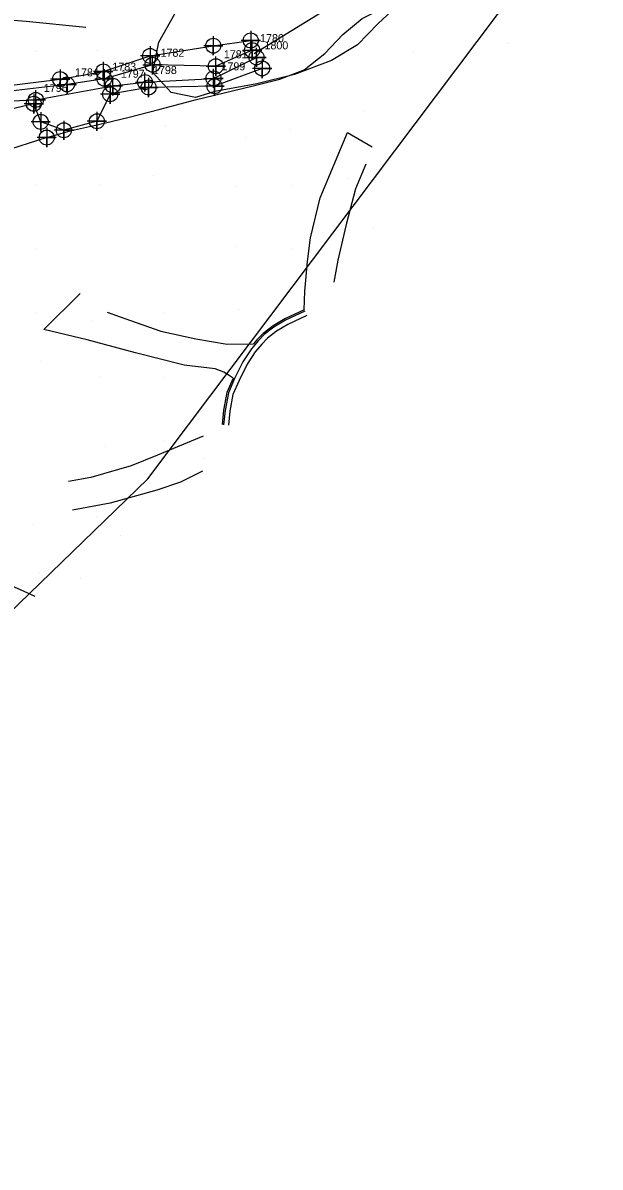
# Model space of a CAD drawing. Extents: x 1497074 to 1501343, y 481943 to 486114.
# Drawn here: x 1498743.8 to 1498924.2, y 484438.2 to 484795.7 of the extents above; entities that cross this region are included whole.
import ezdxf

# ---------------------------------------------------------------- set-up
doc = ezdxf.new("R2010")
doc.units = 0
for name, color, linetype in [('Exist DTM Breakline', 7, 'Continuous'), ('Exist DTM Breakline Cogo Point CELL', 7, 'Continuous'), ('Exist Hydro Stream or Body of Water', 7, 'Continuous'), ('Exist Hydro Stream or Body of Water Cogo Number', 7, 'Continuous'), ('Exist Hydro Stream or Body of Water Cogo Point CELL', 7, 'Continuous'), ('PH Exist DTM Boundary', 7, 'Continuous'), ('PH Exist DTM Breakline', 7, 'Continuous'), ('PH Exist DTM Obscure Area', 7, 'Continuous'), ('PH Exist DTM Point', 7, 'Continuous')]:
    doc.layers.add(name, color=color, linetype=linetype)

msp = doc.modelspace()

# ---------------------------------------------------------------- linework, layer by layer
at = {"layer": 'Exist DTM Breakline'}
for points in [[(1498642.2, 484728.41), (1498666.42, 484741.46), (1498690.37, 484749.54), (1498707.14, 484761.75), (1498724.39, 484768.67), (1498731.03, 484775.11), (1498755.48, 484778.15), (1498768.96, 484780.57), (1498783.61, 484785.4), (1498803.34, 484788.6), (1498815.05, 484790.23)], [(1498818.6, 484781.5), (1498803.72, 484775.91), (1498783.12, 484775.55), (1498771.11, 484773.41), (1498766.97, 484764.97), (1498756.64, 484762.17), (1498749.4, 484764.8), (1498747.24, 484770.45), (1498734.31, 484767.43), (1498718.71, 484759.53), (1498707.65, 484753), (1498690.86, 484741.59), (1498675.18, 484734.94)], [(1498751.28, 484759.9), (1498722.71, 484750.7), (1498697.19, 484737.24), (1498663.06, 484720.07)]]:
    msp.add_lwpolyline(points, dxfattribs=at)
at = {"layer": 'Exist DTM Breakline Cogo Point CELL'}
for points in [[(1498803.34, 484791.6), (1498803.34, 484785.6), (1498803.34, 484788.6), (1498806.34, 484788.6), (1498800.34, 484788.6)], [(1498815.05, 484793.23), (1498815.05, 484787.23), (1498815.05, 484790.23), (1498818.05, 484790.23), (1498812.05, 484790.23)], [(1498783.61, 484788.4), (1498783.61, 484782.4), (1498783.61, 484785.4), (1498786.61, 484785.4), (1498780.61, 484785.4)], [(1498818.6, 484784.5), (1498818.6, 484778.5), (1498818.6, 484781.5), (1498821.6, 484781.5), (1498815.6, 484781.5)], [(1498755.48, 484781.15), (1498755.48, 484775.15), (1498755.48, 484778.15), (1498758.48, 484778.15), (1498752.48, 484778.15)], [(1498768.96, 484783.57), (1498768.96, 484777.57), (1498768.96, 484780.57), (1498771.96, 484780.57), (1498765.96, 484780.57)], [(1498783.12, 484778.55), (1498783.12, 484772.55), (1498783.12, 484775.55), (1498786.12, 484775.55), (1498780.12, 484775.55)], [(1498803.72, 484778.91), (1498803.72, 484772.91), (1498803.72, 484775.91), (1498806.72, 484775.91), (1498800.72, 484775.91)], [(1498747.24, 484773.45), (1498747.24, 484767.45), (1498747.24, 484770.45), (1498750.24, 484770.45), (1498744.24, 484770.45)], [(1498771.11, 484776.41), (1498771.11, 484770.41), (1498771.11, 484773.41), (1498774.11, 484773.41), (1498768.11, 484773.41)], [(1498749.4, 484767.8), (1498749.4, 484761.8), (1498749.4, 484764.8), (1498752.4, 484764.8), (1498746.4, 484764.8)], [(1498766.97, 484767.97), (1498766.97, 484761.97), (1498766.97, 484764.97), (1498769.97, 484764.97), (1498763.97, 484764.97)], [(1498751.28, 484762.9), (1498751.28, 484756.9), (1498751.28, 484759.9), (1498754.28, 484759.9), (1498748.28, 484759.9)], [(1498756.64, 484765.17), (1498756.64, 484759.17), (1498756.64, 484762.17), (1498759.64, 484762.17), (1498753.64, 484762.17)]]:
    msp.add_lwpolyline(points, dxfattribs=at)
for centre in [(1498803.34, 484788.6), (1498815.05, 484790.23), (1498783.61, 484785.4), (1498818.6, 484781.5), (1498755.48, 484778.15), (1498768.96, 484780.57), (1498783.12, 484775.55), (1498803.72, 484775.91), (1498771.11, 484773.41), (1498747.24, 484770.45), (1498749.4, 484764.8), (1498766.97, 484764.97), (1498756.64, 484762.17), (1498751.28, 484759.9)]:
    msp.add_circle(centre, 2.34, dxfattribs=at)
at = {"layer": 'Exist Hydro Stream or Body of Water'}
for points in [[(1498815.48, 484787.21), (1498804.14, 484782.17), (1498784.36, 484782.64), (1498769.3, 484778.28), (1498757.64, 484776.52), (1498731.04, 484773.39), (1498724.7, 484767.33), (1498709.42, 484760.65), (1498690.59, 484748.07), (1498666.52, 484739.44), (1498641.87, 484726.36)], [(1498672.43, 484739.05), (1498689.81, 484742.76), (1498705.79, 484752.75), (1498717.83, 484761.59), (1498732.54, 484771.06), (1498747.88, 484771.66), (1498771.96, 484776.08), (1498782, 484777.24), (1498803.41, 484778.39), (1498816.84, 484784.96)]]:
    msp.add_lwpolyline(points, dxfattribs=at)
at = {"layer": 'Exist Hydro Stream or Body of Water Cogo Point CELL'}
for points in [[(1498812.48, 484787.21), (1498818.48, 484787.21), (1498815.48, 484787.21), (1498815.48, 484784.21), (1498815.48, 484790.21)], [(1498813.84, 484784.96), (1498819.84, 484784.96), (1498816.84, 484784.96), (1498816.84, 484781.96), (1498816.84, 484787.96)], [(1498781.36, 484782.64), (1498787.36, 484782.64), (1498784.36, 484782.64), (1498784.36, 484779.64), (1498784.36, 484785.64)], [(1498801.14, 484782.17), (1498807.14, 484782.17), (1498804.14, 484782.17), (1498804.14, 484779.17), (1498804.14, 484785.17)], [(1498766.3, 484778.28), (1498772.3, 484778.28), (1498769.3, 484778.28), (1498769.3, 484775.28), (1498769.3, 484781.28)], [(1498779, 484777.24), (1498785, 484777.24), (1498782, 484777.24), (1498782, 484774.24), (1498782, 484780.24)], [(1498800.41, 484778.39), (1498806.41, 484778.39), (1498803.41, 484778.39), (1498803.41, 484775.39), (1498803.41, 484781.39)], [(1498754.64, 484776.52), (1498760.64, 484776.52), (1498757.64, 484776.52), (1498757.64, 484773.52), (1498757.64, 484779.52)], [(1498768.96, 484776.08), (1498774.96, 484776.08), (1498771.96, 484776.08), (1498771.96, 484773.08), (1498771.96, 484779.08)], [(1498744.88, 484771.66), (1498750.88, 484771.66), (1498747.88, 484771.66), (1498747.88, 484768.66), (1498747.88, 484774.66)]]:
    msp.add_lwpolyline(points, dxfattribs=at)
for centre in [(1498815.48, 484787.21), (1498784.36, 484782.64), (1498804.14, 484782.17), (1498816.84, 484784.96), (1498769.3, 484778.28), (1498803.41, 484778.39), (1498757.64, 484776.52), (1498771.96, 484776.08), (1498782, 484777.24), (1498747.88, 484771.66)]:
    msp.add_circle(centre, 2.34, dxfattribs=at)
at = {"layer": 'PH Exist DTM Boundary'}
msp.add_lwpolyline([(1498186.43, 484771.69), (1498560.82, 484438.23), (1498782.89, 484653.31), (1498924.23, 484841.06), (1498545.19, 485168.9), (1498406.94, 484985.26)], close=True, dxfattribs=at)
at = {"layer": 'PH Exist DTM Breakline'}
for points in [[(1498871.75, 484817.91), (1498862.06, 484812.48), (1498844.48, 484803.59), (1498816.16, 484786.08)], [(1498751.28, 484759.9), (1498758.99, 484762.13), (1498767.46, 484763.96), (1498776.63, 484766.15), (1498786.71, 484768.77), (1498797.68, 484771.65), (1498806.73, 484773.91), (1498815.79, 484776.07), (1498824.19, 484778.19), (1498831.77, 484781.06), (1498838.18, 484786.15), (1498843.82, 484792.08), (1498849.87, 484797.11), (1498857.7, 484800.99), (1498865.48, 484804.27), (1498872, 484807.32), (1498879.68, 484809.61), (1498887.65, 484811.86), (1498895.42, 484813.08), (1498901.06, 484810.76), (1498906.62, 484808.24), (1498910.07, 484805.42)], [(1498763.56, 484794.31), (1498744.83, 484796.11), (1498738.07, 484796.71), (1498731.78, 484797.17), (1498724.97, 484796.7), (1498717.62, 484795.94), (1498710.92, 484795.54), (1498704.32, 484795.61), (1498698.28, 484794.78), (1498694.33, 484791.72), (1498692.02, 484789.28), (1498685.41, 484785.03), (1498678.23, 484782.05), (1498671.57, 484779.37), (1498664.71, 484774.06), (1498660.11, 484769.43), (1498655.29, 484764.35), (1498651.54, 484760.4), (1498646.8, 484755.42), (1498641.81, 484751.48), (1498635.97, 484749.35), (1498631.53, 484748.05)], [(1498831.7, 484706.11), (1498831.94, 484711.95), (1498832.79, 484721.19), (1498833.7, 484728.53), (1498836.74, 484741.07), (1498845.25, 484761.45), (1498853.04, 484757.03)], [(1498851.04, 484751.56), (1498847.76, 484743.92), (1498844.85, 484732.68), (1498842.31, 484721.64), (1498841.02, 484714.68)], [(1498809.52, 484684.7), (1498808.28, 484685.55), (1498806.62, 484686.62), (1498803.94, 484687.59), (1498794.24, 484688.74), (1498779.01, 484692.68), (1498763.93, 484696.65), (1498750.41, 484699.93), (1498761.7, 484711.15)], [(1498770.2, 484705.3), (1498775.72, 484703.39), (1498786.9, 484699.39), (1498797.85, 484697.02), (1498807.72, 484695.33), (1498815.94, 484695.43)], [(1498831.91, 484705.66), (1498825.92, 484702.84), (1498822.3, 484700.64), (1498819.28, 484698.34), (1498817.36, 484696.34), (1498815.26, 484693.84), (1498812.62, 484689.83), (1498810.02, 484684.61), (1498808.06, 484680.11), (1498807.05, 484674.63), (1498806.57, 484670.17)], [(1498831.7, 484706.11), (1498825.68, 484703.28), (1498822.02, 484701.05), (1498818.95, 484698.72), (1498816.99, 484696.67), (1498815.94, 484695.43)], [(1498832.55, 484704.3), (1498826.63, 484701.52), (1498823.14, 484699.4), (1498820.28, 484697.22), (1498818.47, 484695.33), (1498816.46, 484692.94), (1498813.93, 484689.08), (1498811.38, 484683.97), (1498809.5, 484679.67), (1498808.54, 484674.42), (1498808.06, 484670.01)], [(1498809.52, 484684.7), (1498807.57, 484680.26), (1498806.56, 484674.71), (1498806.07, 484670.23)], [(1498631.32, 484672.18), (1498638.78, 484668.07), (1498645.74, 484665.05), (1498652.08, 484662.44), (1498658.02, 484661.42), (1498665.09, 484661.49), (1498671.48, 484661.91), (1498678.83, 484660.27), (1498685.67, 484657.51), (1498691.48, 484653.45), (1498698.1, 484647.25), (1498704.19, 484641.46), (1498707.27, 484638.54), (1498711.94, 484634.11), (1498717.33, 484630.4), (1498724.54, 484626.58), (1498731.01, 484623.87), (1498736.56, 484621.51), (1498742.96, 484618.72), (1498747.59, 484616.58)], [(1498800.15, 484666.61), (1498785.86, 484660.65), (1498777.65, 484657.29), (1498765.05, 484653.71), (1498758.06, 484652.4)], [(1498800.02, 484655.67), (1498793.13, 484652.23), (1498785.75, 484649.71), (1498771.16, 484645.66), (1498759.31, 484643.49)]]:
    msp.add_lwpolyline(points, dxfattribs=at)
at = {"layer": 'PH Exist DTM Obscure Area'}
msp.add_lwpolyline([(1498861.95, 484802.08), (1498854.91, 484795.57), (1498848.38, 484788.87), (1498840.26, 484784.01), (1498828.76, 484779.63), (1498816.98, 484776.72), (1498803.86, 484774.24), (1498797.81, 484772.45), (1498790.17, 484774.01), (1498784.47, 484780.19), (1498786.33, 484789.65), (1498791.34, 484798.56)], dxfattribs=at)
at = {"layer": 'PH Exist DTM Point'}
for p, q in [((1498784.47, 484790.24), (1498784.47, 484790.24)), ((1498895.52, 484789.19), (1498895.52, 484789.19)), ((1498747.67, 484786.71), (1498747.67, 484786.71)), ((1498767.11, 484787.19), (1498767.11, 484787.19)), ((1498866.05, 484786.83), (1498866.05, 484786.83)), ((1498850.51, 484768), (1498850.51, 484768)), ((1498788.34, 484763.68), (1498788.34, 484763.68)), ((1498827.45, 484762.29), (1498827.45, 484762.29)), ((1498768.33, 484759.45), (1498768.33, 484759.45)), ((1498813.51, 484759.99), (1498813.51, 484759.99)), ((1498784.8, 484748.02), (1498784.8, 484748.02)), ((1498747.81, 484745.16), (1498747.81, 484745.16)), ((1498767.81, 484745.16), (1498767.81, 484745.16)), ((1498810.15, 484744.51), (1498810.15, 484744.51)), ((1498827.97, 484745.01), (1498827.97, 484745.01)), ((1498845.61, 484747.25), (1498845.61, 484747.25)), ((1498853.4, 484731.52), (1498853.4, 484731.52)), ((1498747.68, 484725.28), (1498747.68, 484725.28)), ((1498810.31, 484725.82), (1498810.31, 484725.82)), ((1498827.9, 484725.08), (1498827.9, 484725.08)), ((1498747.81, 484705.16), (1498747.81, 484705.16)), ((1498787.81, 484705.16), (1498787.81, 484705.16)), ((1498811.12, 484706.16), (1498811.12, 484706.16)), ((1498765.38, 484702.65), (1498765.38, 484702.65)), ((1498749.28, 484690.02), (1498749.28, 484690.02)), ((1498767.91, 484685.11), (1498767.91, 484685.11)), ((1498788.04, 484684.95), (1498788.04, 484684.95)), ((1498769.7, 484663.37), (1498769.7, 484663.37)), ((1498787.81, 484665.16), (1498787.81, 484665.16)), ((1498800.37, 484659.62), (1498800.37, 484659.62)), ((1498766.94, 484641.39), (1498766.94, 484641.39)), ((1498747.02, 484639.05), (1498747.02, 484639.05)), ((1498774.23, 484635.69), (1498774.23, 484635.69)), ((1498749.01, 484624.02), (1498749.01, 484624.02)), ((1498761.72, 484622.15), (1498761.72, 484622.15))]:
    msp.add_line(p, q, dxfattribs=at)

# ---------------------------------------------------------------- texts
at = {"layer": 'Exist Hydro Stream or Body of Water Cogo Number'}
for s, p in [('1780', (1498817.98, 484789.71)), ('1782', (1498786.86, 484785.14)), ('1800', (1498819.34, 484787.46)), ('1781', (1498806.64, 484784.67)), ('1784', (1498760.14, 484779.02)), ('1783', (1498771.8, 484780.79)), ('1797', (1498774.46, 484778.58)), ('1798', (1498784.5, 484779.74)), ('1799', (1498805.91, 484780.9)), ('1796', (1498750.38, 484774.16))]:
    msp.add_text(s, height=2.5, dxfattribs=at).set_placement(p)

doc.saveas('drawing.dxf')
